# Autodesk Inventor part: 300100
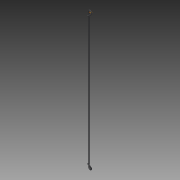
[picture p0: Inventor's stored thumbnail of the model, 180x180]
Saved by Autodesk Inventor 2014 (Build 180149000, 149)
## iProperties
Created: 2007-11
Part Number: 300100
Document SubType Name: Modeling
Designer: TH
Density: 8.08 g/cm^3
Mass: 7.827 g
Surface Area: 19.058 cm^2
Volume: 0.968688 cm^3
Material: Stainless Steel
Description: WIRE MIDDLE
Appearance: Gray
Component Category: Back Component
Author: TH
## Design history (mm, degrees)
sketch "Sketch1"
  geometry: C1 r 1.016 at (0, 0); 1 further point
  constraints: 1 centre point, 1 coincident
  dimensions: "d0" = 2.032 diameter of C1
extrude "Extrusion1" new body sketch "Sketch1" stored distance "d3" = 260; taper "d4" = 0 deg
sketch "Sketch4"
  geometry: C1 r 1.016 at (0, 0) reference
sketch "Sketch5"
  geometry: L1 (1.016, 130)-(-1.016, 130) reference; L2 (0, 130)-(-3.266, 130); 1 further point
  constraints: 2 end point, 1 collinear, 1 midpoint
  dimensions: "d9" = 3.266 distance of L2.start L2.end
workaxis "Work Axis1"
  workpoint "Work Point1"
coil "Coil1" pitch "d10" = 4; turns "d12" = 0.65; dims "d11" = 10, "d13" = 0, angle "d14" = 90 deg, angle "d15" = 90 deg, "d16" = 0, "d17" = 0
sketch "Sketch6"
  geometry: 3 further points
  constraints: 1 horizontal alignment
extrude "Extrusion2" join sketch "Sketch6" distance "d18" = 6; taper "d19" = 0 deg
fillet "Fillet1" dims "d20" = 0.5, "d21" = 1
mirror "Mirror1"
body "Solid1"
